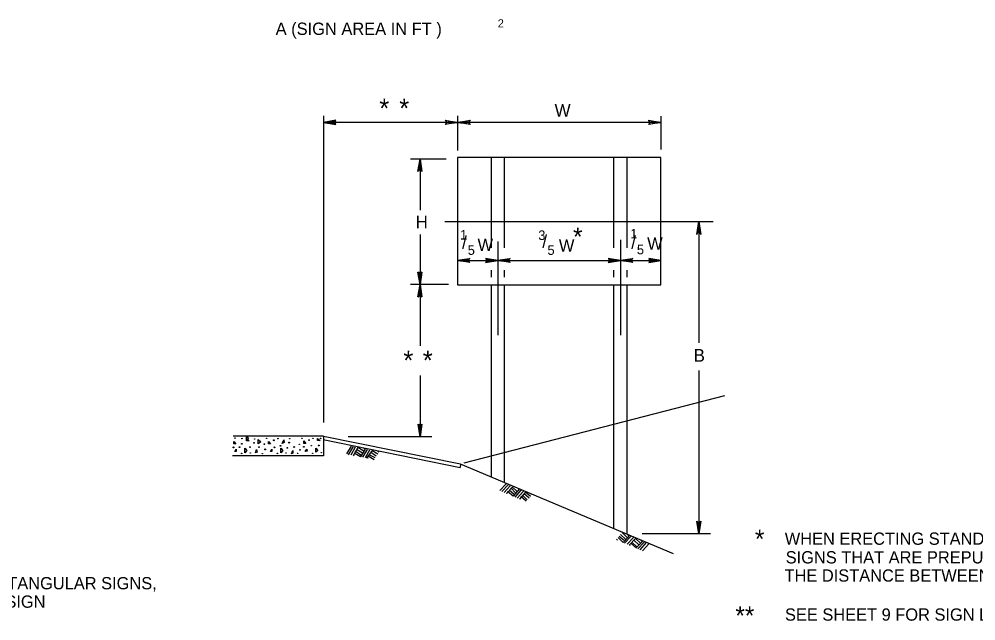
# Model space of a CAD drawing. Extents: x 644358 to 648627, y 294594 to 295782.
# Drawn here: x 645520.7 to 645754.7, y 294895.9 to 295043 of the extents above; entities that cross this region are included whole.
import ezdxf

# ---------------------------------------------------------------- set-up
doc = ezdxf.new("R2010")
doc.units = 0
for name, color, linetype in [('1', 7, 'Continuous'), ('2', 7, 'Continuous'), ('3', 7, 'Continuous'), ('4', 7, 'Continuous')]:
    doc.layers.add(name, color=color, linetype=linetype)

# ---------------------------------------------------------------- blocks, each defined once
blk = doc.blocks.new('RARROW')
at = {"layer": '3'}
blk.add_lwpolyline([(-2.2695, 0.285), (-2.184875, 0.12075), (0, 0), (-2.2695, 0.285), (-2.38575, 0.384625), (0, 0), (-2.183125, -0.108), (-2.262875, -0.2705), (0, 0), (-2.38575, -0.379125), (-2.262875, -0.2705)], dxfattribs=at)

msp = doc.modelspace()

# ---------------------------------------------------------------- linework, layer by layer
at = {"layer": '1'}
for p, q in [((645627.94, 294977.98), (645627.94, 294977.98)), ((645601.94, 294938.6), (645600.81, 294936.73)), ((645602.44, 294938.48), (645601.19, 294936.48)), ((645602.94, 294938.35), (645601.81, 294936.35)), ((645603.56, 294938.23), (645602.44, 294936.23)), ((645604.31, 294936.35), (645602.94, 294937.35)), ((645604.69, 294936.85), (645603.19, 294937.73)), ((645605.06, 294937.35), (645603.56, 294938.23)), ((645605.31, 294937.85), (645604.19, 294935.98)), ((645605.81, 294937.73), (645604.69, 294935.85)), ((645605.31, 294937.73), (645605.06, 294937.98)), ((645606.44, 294937.6), (645605.31, 294935.73)), ((645607.06, 294937.48), (645605.69, 294935.6)), ((645608.06, 294936.1), (645606.69, 294937.1)), ((645608.44, 294936.6), (645606.94, 294937.48)), ((645608.69, 294937.1), (645608.44, 294937.35)), ((645602.69, 294936.23), (645602.44, 294936.35)), ((645604.19, 294935.98), (645602.69, 294936.85)), ((645606.06, 294935.6), (645605.69, 294935.73)), ((645607.56, 294935.23), (645606.06, 294936.1)), ((645607.81, 294935.73), (645606.31, 294936.48)), ((645639.81, 294929.35), (645638.31, 294927.73)), ((645640.31, 294929.1), (645638.81, 294927.48)), ((645640.81, 294928.85), (645639.31, 294927.23)), ((645641.44, 294928.6), (645639.94, 294926.98)), ((645641.81, 294926.73), (645640.56, 294927.85)), ((645642.19, 294927.1), (645640.94, 294928.35)), ((645642.56, 294927.48), (645641.31, 294928.6)), ((645643.06, 294928.1), (645641.56, 294926.35)), ((645643.44, 294927.85), (645641.94, 294926.1)), ((645644.06, 294927.6), (645642.56, 294925.85)), ((645642.94, 294927.98), (645642.81, 294928.23)), ((645640.19, 294926.98), (645639.94, 294927.1)), ((645641.56, 294926.35), (645640.19, 294927.48)), ((645644.56, 294927.35), (645643.06, 294925.6)), ((645643.19, 294925.6), (645643.19, 294925.73)), ((645644.69, 294925.1), (645643.44, 294926.23)), ((645644.94, 294925.48), (645643.81, 294926.6)), ((645645.44, 294925.85), (645644.19, 294926.98)), ((645645.81, 294926.23), (645644.56, 294927.35)), ((645646.19, 294926.73), (645645.94, 294926.85)), ((645667.06, 294915.6), (645666.81, 294915.85)), ((645668.44, 294914.98), (645667.19, 294916.23)), ((645668.69, 294915.48), (645667.44, 294916.48)), ((645669.06, 294915.85), (645667.81, 294916.98)), ((645669.44, 294916.23), (645668.19, 294917.48)), ((645669.94, 294916.6), (645668.44, 294914.98)), ((645670.31, 294916.48), (645668.81, 294914.85)), ((645670.94, 294916.23), (645669.44, 294914.6)), ((645669.81, 294916.6), (645669.69, 294916.85)), ((645671.44, 294915.98), (645669.94, 294914.35)), ((645672.69, 294914.85), (645671.44, 294915.98)), ((645670.19, 294914.23), (645670.06, 294914.35)), ((645671.69, 294913.6), (645670.31, 294914.85)), ((645671.81, 294913.98), (645670.56, 294915.1)), ((645672.31, 294914.48), (645671.06, 294915.6)), ((645673.19, 294915.23), (645671.56, 294913.6)), ((645673.56, 294915.1), (645672.06, 294913.48)), ((645674.06, 294914.98), (645672.56, 294913.23)), ((645673.06, 294915.23), (645672.81, 294915.48)), ((645674.69, 294914.73), (645673.19, 294912.98))]:
    msp.add_line(p, q, dxfattribs=at)
for points in [[(645598.06, 295018.1), (645597.94, 295017.85), (645595.19, 295017.73), (645598.06, 295018.1), (645598.19, 295018.23), (645595.19, 295017.73), (645597.94, 295017.6), (645598.06, 295017.35), (645595.19, 295017.73), (645598.19, 295017.23), (645598.06, 295017.35)], [(645625.06, 295018.1), (645625.19, 295017.85), (645627.94, 295017.73), (645625.06, 295018.1), (645624.94, 295018.23), (645627.94, 295017.73), (645625.19, 295017.6), (645625.06, 295017.35), (645627.94, 295017.73), (645624.94, 295017.23), (645625.06, 295017.35)], [(645630.94, 295017.35), (645630.81, 295017.6), (645627.94, 295017.73), (645630.94, 295017.35), (645631.06, 295017.23), (645627.94, 295017.73), (645630.81, 295017.85), (645630.94, 295018.1), (645627.94, 295017.73), (645631.06, 295018.23), (645630.94, 295018.1)], [(645674.69, 295018.1), (645674.81, 295017.85), (645677.69, 295017.73), (645674.69, 295018.1), (645674.69, 295018.23), (645677.69, 295017.73), (645674.81, 295017.6), (645674.81, 295017.35), (645677.69, 295017.73), (645674.69, 295017.23), (645674.81, 295017.35)], [(645618.31, 295005.85), (645618.56, 295005.98), (645618.81, 295008.73), (645618.31, 295005.85), (645618.19, 295005.73), (645618.81, 295008.73), (645618.94, 295005.98), (645619.19, 295005.85), (645618.81, 295008.73), (645619.19, 295005.73), (645619.19, 295005.85)], [(645686.56, 294990.6), (645686.69, 294990.73), (645686.94, 294993.48), (645686.56, 294990.6), (645686.44, 294990.35), (645686.94, 294993.48), (645687.06, 294990.73), (645687.31, 294990.6), (645686.94, 294993.48), (645687.44, 294990.35), (645687.31, 294990.6)], [(645619.19, 294981.1), (645618.94, 294980.98), (645618.81, 294978.1), (645619.19, 294981.1), (645619.19, 294981.1), (645618.81, 294978.1), (645618.56, 294980.98), (645618.44, 294981.1), (645618.81, 294978.1), (645618.19, 294981.1), (645618.44, 294981.1)], [(645618.31, 294975.1), (645618.56, 294975.23), (645618.81, 294978.1), (645618.31, 294975.1), (645618.19, 294975.1), (645618.81, 294978.1), (645618.94, 294975.23), (645619.19, 294975.1), (645618.81, 294978.1), (645619.19, 294975.1), (645619.19, 294975.1)], [(645619.19, 294943.85), (645618.94, 294943.73), (645618.81, 294940.85), (645619.19, 294943.85), (645619.19, 294943.98), (645618.81, 294940.85), (645618.69, 294943.73), (645618.44, 294943.85), (645618.81, 294940.85), (645618.31, 294943.98), (645618.44, 294943.85)], [(645687.31, 294919.98), (645687.06, 294919.98), (645686.94, 294917.1), (645687.31, 294919.98), (645687.44, 294920.23), (645686.94, 294917.1), (645686.69, 294919.98), (645686.69, 294919.98), (645686.94, 294917.1), (645686.44, 294920.23), (645686.69, 294919.98)]]:
    msp.add_lwpolyline(points, dxfattribs=at)
for points in [[(645573.19, 294939.1), (645573.19, 294939.73), (645573.69, 294939.1)], [(645576.31, 294939.98), (645576.31, 294940.98), (645576.81, 294940.48)], [(645576.31, 294939.85), (645576.31, 294940.48), (645576.94, 294939.85)], [(645579.19, 294939.1), (645579.19, 294940.23), (645579.81, 294939.6)], [(645581.69, 294939.1), (645581.69, 294939.73), (645582.19, 294939.1)], [(645585.44, 294940.1), (645585.56, 294939.48), (645585.06, 294939.23)], [(645590.31, 294939.23), (645590.31, 294939.85), (645590.81, 294939.23)], [(645593.69, 294939.98), (645593.69, 294940.48), (645594.31, 294939.98)], [(645573.81, 294937.85), (645573.81, 294937.23), (645573.44, 294937.23)], [(645575.94, 294936.98), (645575.94, 294938.1), (645576.44, 294937.48)], [(645578.81, 294937.73), (645578.94, 294937.1), (645578.56, 294936.98)], [(645582.56, 294937.85), (645582.56, 294937.23), (645582.19, 294937.23)], [(645584.69, 294936.98), (645584.69, 294938.1), (645585.19, 294937.48)], [(645587.69, 294937.48), (645587.69, 294936.85), (645587.31, 294936.73)], [(645591.06, 294937.85), (645591.19, 294937.35), (645590.69, 294937.23)], [(645593.31, 294937.1), (645593.31, 294938.1), (645593.81, 294937.48)]]:
    msp.add_lwpolyline(points, close=True, dxfattribs=at)
for centre, radius in [((645573.53, 294940.53), 0.056), ((645575.19, 294939.15), 0.0979), ((645575.22, 294940.43), 0.056), ((645578.16, 294939.39), 0.0979), ((645578.31, 294940.34), 0.056), ((645581.26, 294940.46), 0.056), ((645583.01, 294940.01), 0.0979), ((645583.99, 294940.43), 0.056), ((645586.76, 294939.44), 0.0979), ((645586.91, 294940.39), 0.056), ((645589.86, 294940.51), 0.056), ((645591.6, 294940.06), 0.0979), ((645592.59, 294940.48), 0.056), ((645594.43, 294940.45), 0.056), ((645573.14, 294938.27), 0.0979), ((645574.64, 294938.34), 0.0979), ((645577.17, 294938.31), 0.0979), ((645577.24, 294936.91), 0.056), ((645579.39, 294938.32), 0.0979), ((645580.69, 294939.07), 0.0979), ((645580.91, 294937.78), 0.0979), ((645583.19, 294938.29), 0.0979), ((645584.66, 294938.65), 0.0979), ((645586.01, 294936.91), 0.056), ((645586.32, 294938.16), 0.0979), ((645587.98, 294938.37), 0.0979), ((645589.27, 294939), 0.056), ((645589.41, 294937.65), 0.0979), ((645590.34, 294938.42), 0.0979), ((645592.15, 294938.67), 0.056), ((645592.5, 294936.83), 0.056), ((645593.99, 294938.75), 0.0979), ((645594.61, 294936.96), 0.056), ((645575.13, 294936.78), 0.056), ((645580.22, 294936.75), 0.056), ((645583.9, 294936.78), 0.056), ((645588.81, 294936.8), 0.056)]:
    msp.add_circle(centre, radius, dxfattribs=at)
at = {"layer": '2'}
for p, q in [((645627.94, 295009.1), (645627.94, 294977.98)), ((645677.69, 295009.1), (645627.94, 295009.1)), ((645636.19, 295009.1), (645636.19, 294987.02)), ((645639.31, 295009.1), (645639.31, 294987.02)), ((645666.06, 295009.1), (645666.06, 294987.02)), ((645669.31, 295009.1), (645669.31, 294987.02)), ((645677.69, 294977.98), (645677.69, 295009.1)), ((645637.81, 294988.6), (645637.81, 294965.73)), ((645667.81, 294988.98), (645667.81, 294965.73)), ((645627.94, 294983.98), (645637.81, 294983.98)), ((645637.81, 294983.98), (645667.81, 294983.98)), ((645667.81, 294983.98), (645677.69, 294983.98)), ((645636.19, 294981.62), (645636.19, 294979.87)), ((645639.31, 294981.62), (645639.31, 294979.87)), ((645666.06, 294981.62), (645666.06, 294979.87)), ((645669.31, 294981.62), (645669.31, 294979.87)), ((645627.94, 294977.98), (645627.94, 294977.98)), ((645627.94, 294977.98), (645677.69, 294977.98)), ((645627.94, 294977.98), (645627.94, 294977.98)), ((645636.19, 294977.85), (645636.19, 294930.98)), ((645637.81, 294977.98), (645637.81, 294977.98)), ((645639.31, 294977.98), (645639.31, 294929.73)), ((645666.06, 294977.98), (645666.06, 294918.35)), ((645667.81, 294977.98), (645667.81, 294977.98)), ((645669.31, 294977.85), (645669.31, 294917.1)), ((645677.31, 294977.98), (645677.31, 294977.98)), ((645629.56, 294934.48), (645693.31, 294950.98)), ((645595.19, 294940.98), (645573.06, 294940.98)), ((645595.06, 294940.23), (645628.56, 294933.35)), ((645595.19, 294940.98), (645628.69, 294934.23)), ((645595.19, 294940.98), (645595.19, 294936.23)), ((645595.19, 294936.23), (645572.94, 294936.23)), ((645628.56, 294934.23), (645680.69, 294912.35)), ((645628.69, 294934.23), (645628.56, 294933.35)), ((645628.69, 294934.23), (645628.56, 294933.35))]:
    msp.add_line(p, q, dxfattribs=at)
at = {"layer": '4'}
for p, q in [((645595.19, 295019.35), (645595.19, 294944.35)), ((645627.94, 295019.35), (645627.94, 295010.85)), ((645677.69, 295019.23), (645677.69, 295011.1)), ((645627.94, 295017.73), (645595.19, 295017.73)), ((645677.69, 295017.73), (645627.94, 295017.73)), ((645625.19, 295008.73), (645616.44, 295008.73)), ((645618.81, 295008.73), (645618.81, 294996.23)), ((645624.81, 294993.48), (645690.44, 294993.48)), ((645686.94, 294993.48), (645686.94, 294963.85)), ((645618.81, 294990.35), (645618.81, 294978.1)), ((645625.69, 294978.1), (645616.44, 294978.1)), ((645618.81, 294978.1), (645618.81, 294963.1)), ((645618.81, 294955.85), (645618.81, 294940.85)), ((645686.94, 294957.1), (645686.94, 294917.1)), ((645621.69, 294940.85), (645601.19, 294940.85)), ((645689.81, 294917.1), (645673.06, 294917.1))]:
    msp.add_line(p, q, dxfattribs=at)

# ---------------------------------------------------------------- block references
at = {"layer": '2', "xscale": 1.2574347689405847, "yscale": 1.3092961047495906, "rotation": 180}
for p in [(645627.94, 294983.98), (645637.81, 294983.98), (645667.81, 294983.98)]:
    msp.add_blockref('RARROW', p, dxfattribs=at)
at = {"layer": '2', "xscale": 1.2574347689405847, "yscale": -1.3092961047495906}
for p in [(645637.81, 294983.98), (645667.81, 294983.98), (645677.69, 294983.98)]:
    msp.add_blockref('RARROW', p, dxfattribs=at)

# ---------------------------------------------------------------- texts
at = {"layer": '3'}
msp.add_text('SEE SHEET 9 FOR SIGN LOCATION/INSTALLATION', height=3, dxfattribs=at).set_placement((645708.03, 294895.91))
at = {"layer": '4'}
for s, height, p in [('A (SIGN AREA IN FT )', 3.005, (645583.46, 295039.11)), ('2', 2, (645637.78, 295040.93)), ('*', 4.68, (645608.81, 295018.85)), ('*', 4.68, (645613.69, 295018.85)), ('W', 3.09, (645651.69, 295019.1)), ('H', 3.09, (645617.69, 294991.85)), ('1', 2.34, (645628.56, 294989.09)), ('3', 2.34, (645647.69, 294988.97)), ('*', 4.45, (645656.19, 294987.55)), ('1', 2.34, (645670.19, 294989.34)), ('/', 3.11, (645629.06, 294986.84)), ('W', 3, (645632.84, 294986.29)), ('/', 3.11, (645648.69, 294987.09)), ('W', 3, (645652.73, 294986.12)), ('/', 3.11, (645670.44, 294986.84)), ('W', 3, (645674.33, 294986.59)), ('5', 2.34, (645630.44, 294985.34)), ('5', 2.34, (645649.94, 294985.34)), ('5', 2.34, (645671.81, 294985.47)), ('*', 4.68, (645614.69, 294957.23)), ('*', 4.68, (645619.44, 294957.23)), ('B', 3.09, (645685.69, 294959.23)), ('*', 4.45, (645700.68, 294913.68)), ('WHEN ERECTING STANDARD WARNING OR REGULATORY', 3, (645707.97, 294914.46)), ('SIGNS THAT ARE PREPUNCHED, THIS DISTANCE IS', 3, (645708.2, 294909.9)), ('A = W x H FOR SQUARE OR RECTANGULAR SIGNS,', 3, (645455.29, 294903.57)), ('THE DISTANCE BETWEEN THE HORIZONTAL HOLES.', 3, (645707.91, 294905.45)), ('              WHERE: W = WIDTH OF SIGN', 3, (645455.29, 294899.07)), ('**', 4.45, (645695.9, 294894.93))]:
    msp.add_text(s, height=height, dxfattribs=at).set_placement(p)

doc.saveas('drawing.dxf')
